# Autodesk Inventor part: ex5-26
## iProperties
Created: 2006-03
Part Number: ex5-26
Document SubType Name: Modeling
Designer: Elise Moss
Material: Aluminum-6061
Categories: <MemberInstance><Categories><Category DisplayName="Fasteners" InternalName="e4da775c-781d-43d5-af7c-5136215cf5a6" Mnemonic="FSTN"><Category DisplayName="Washers
ATVersion: 1
Author: Elise Moss
Title: SPACER
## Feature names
1. Thickness [Extrusion]
